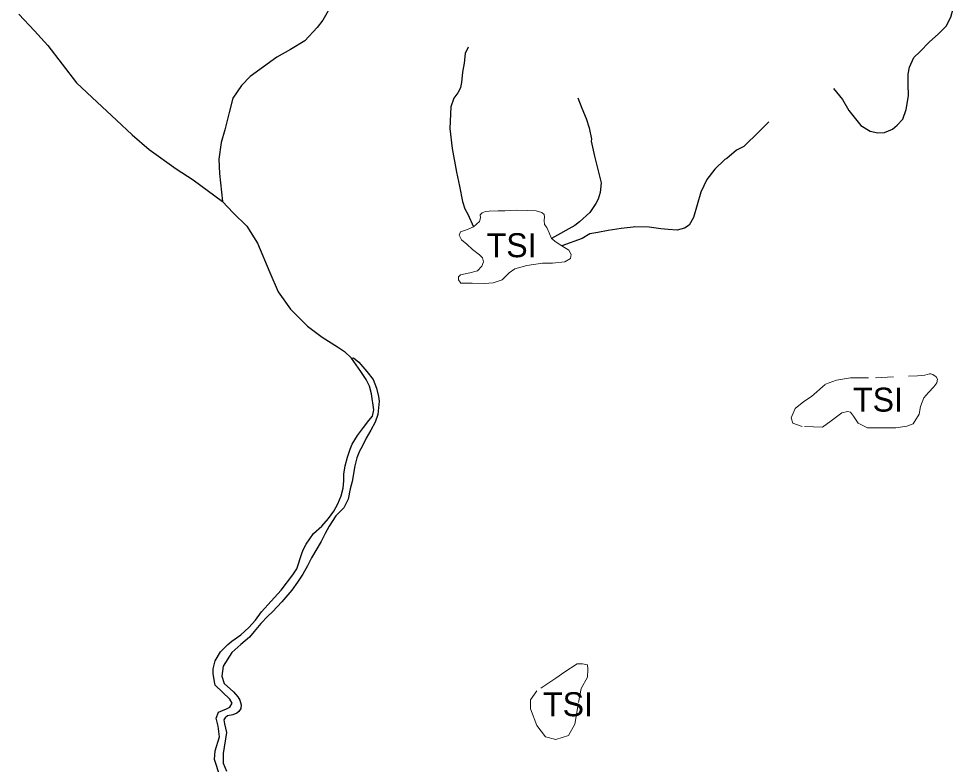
# Model space of a CAD drawing. Extents: x 436.3 to 500.4, y 8231 to 8286.4.
# Drawn here: x 491.46 to 497.73, y 8272.92 to 8277.89 of the extents above; entities that cross this region are included whole.
import ezdxf
from ezdxf.enums import TextEntityAlignment as Align

# ---------------------------------------------------------------- set-up
doc = ezdxf.new("R2010")
doc.units = 0
doc.header["$LTSCALE"] = 0.08
doc.linetypes.add('LONG_DASHED', pattern=[7.5, 6, -1.5])
doc.linetypes.add('SHORT_DASHED', pattern=[2.7, 1.5, -1.2])
for name, color, linetype, lineweight in [('2', 7, 'Continuous', 25), ('21', 7, 'SHORT_DASHED', 13), ('9', 7, 'LONG_DASHED', 25)]:
    doc.layers.add(name, color=color, linetype=linetype, lineweight=lineweight)
doc.layers.add('61', color=7, linetype='Continuous')

msp = doc.modelspace()

# ---------------------------------------------------------------- linework, layer by layer
at = {"layer": '2'}
for points in [[(493.6793, 8275.6241), (493.6916, 8275.6257), (493.7272, 8275.5962), (493.7819, 8275.535), (493.8229, 8275.4802), (493.8449, 8275.4222), (493.8584, 8275.3681), (493.8628, 8275.3366), (493.8538, 8275.2465), (493.8357, 8275.197), (493.8087, 8275.143), (493.7772, 8275.089), (493.7501, 8275.035), (493.7321, 8275.0034), (493.7141, 8274.9584), (493.7005, 8274.9043), (493.6825, 8274.8006), (493.669, 8274.751), (493.6555, 8274.6834), (493.6285, 8274.6248), (493.5744, 8274.5707), (493.5294, 8274.5032), (493.5024, 8274.4536), (493.4754, 8274.3994), (493.4124, 8274.2912), (493.3854, 8274.2371), (493.3538, 8274.1829), (493.3178, 8274.1288), (493.2796, 8274.0754), (493.2143, 8273.998), (493.1513, 8273.9304), (493.1198, 8273.9033), (493.0748, 8273.8537), (493.0298, 8273.7996), (492.9983, 8273.7635), (492.9398, 8273.7139), (492.8813, 8273.6597), (492.8228, 8273.5694), (492.8138, 8273.5016), (492.8294, 8273.4538), (492.8904, 8273.3975), (492.921, 8273.3652), (492.9344, 8273.3415), (492.9423, 8273.3117), (492.9396, 8273.2877), (492.9263, 8273.2663), (492.913, 8273.2557), (492.8864, 8273.2451), (492.8518, 8273.2371), (492.8358, 8273.2238), (492.8278, 8273.2104), (492.8319, 8273.1851), (492.8454, 8273.1263), (492.8229, 8272.9862), (492.8229, 8272.9229), (492.8454, 8272.8686)], [(493.6285, 8274.8504), (493.6375, 8274.9045), (493.651, 8274.9631), (493.669, 8275.0172), (493.6826, 8275.0487), (493.7186, 8275.1072), (493.7592, 8275.1612), (493.7949, 8275.207), (493.8181, 8275.2363), (493.8268, 8275.2781), (493.8133, 8275.3863), (493.7999, 8275.4359), (493.7774, 8275.481), (493.7414, 8275.5352), (493.6793, 8275.6241)], [(493.5249, 8274.5528), (493.5609, 8274.6024), (493.5879, 8274.652), (493.6105, 8274.7061), (493.624, 8274.7557), (493.6285, 8274.8053), (493.6285, 8274.8504)], [(492.8004, 8272.837), (492.7644, 8272.9456), (492.7689, 8273.0043), (492.7982, 8273.0979), (492.789, 8273.1692), (492.7751, 8273.222), (492.7921, 8273.2622), (492.8454, 8273.2846), (492.868, 8273.2967), (492.8835, 8273.323), (492.868, 8273.3494), (492.7688, 8273.4429), (492.7643, 8273.4655), (492.7553, 8273.5198), (492.7553, 8273.5514), (492.7688, 8273.6057), (492.8048, 8273.6644), (492.8543, 8273.714), (492.8813, 8273.7366), (492.9398, 8273.7771), (492.9938, 8273.8268), (493.0388, 8273.8764), (493.0793, 8273.9305), (493.1423, 8274.0027), (493.2098, 8274.0749), (493.2863, 8274.1786), (493.3133, 8274.2192), (493.3493, 8274.3275), (493.3583, 8274.3501), (493.3763, 8274.3816), (493.4258, 8274.4538), (493.4799, 8274.5033), (493.5249, 8274.5528)]]:
    msp.add_lwpolyline(points, dxfattribs=at)
at = {"layer": '21'}
for points in [[(494.5383, 8276.5782), (494.5386, 8276.5592), (494.5331, 8276.5346), (494.4918, 8276.4992)], [(495.0138, 8276.4213), (494.9974, 8276.4597), (494.981, 8276.4954), (494.9673, 8276.5145), (494.9646, 8276.542), (494.9674, 8276.5666), (494.9646, 8276.5803), (494.9482, 8276.594), (494.9098, 8276.605), (494.8548, 8276.6078), (494.7779, 8276.6108), (494.7009, 8276.6055), (494.6569, 8276.6056), (494.5964, 8276.603), (494.5723, 8276.6005), (494.5607, 8276.5972), (494.5516, 8276.593), (494.5383, 8276.5782)], [(494.4918, 8276.4992), (494.445, 8276.48), (494.4065, 8276.4665), (494.3982, 8276.4446), (494.4119, 8276.4117), (494.4476, 8276.3842), (494.486, 8276.3485), (494.5327, 8276.3127), (494.5519, 8276.2935), (494.5601, 8276.2661), (494.5491, 8276.236), (494.5188, 8276.2059), (494.4693, 8276.1923), (494.406, 8276.1787), (494.3923, 8276.1651), (494.3923, 8276.1459), (494.4087, 8276.1239), (494.4829, 8276.1237), (494.5654, 8276.1208), (494.6231, 8276.1262), (494.6836, 8276.1452), (494.7305, 8276.1917), (494.7689, 8276.219), (494.8486, 8276.2408), (494.9531, 8276.257), (495.0191, 8276.2569), (495.1015, 8276.2651), (495.14, 8276.2869), (495.1455, 8276.3143), (495.1291, 8276.3445), (495.0824, 8276.3719)], [(495.0824, 8276.3719), (495.044, 8276.3966), (495.0138, 8276.4213)]]:
    msp.add_lwpolyline(points, dxfattribs=at)
for points in [[(497.544, 8275.5184), (497.5578, 8275.5145), (497.5801, 8275.499), (497.5883, 8275.4842), (497.5851, 8275.4578), (497.5643, 8275.4316), (497.5279, 8275.395), (497.4967, 8275.3583), (497.476, 8275.301), (497.4655, 8275.2488), (497.4265, 8275.1842), (497.3831, 8275.1701), (497.3097, 8275.1597), (497.2421, 8275.1595), (497.1225, 8275.1591), (497.0602, 8275.1903), (497.0291, 8275.2371), (497.0083, 8275.2631), (496.9875, 8275.2682), (496.9511, 8275.2577), (496.8784, 8275.2055), (496.8211, 8275.1636), (496.6859, 8275.1685), (496.6236, 8275.1893), (496.6132, 8275.2258), (496.6392, 8275.2884), (496.6964, 8275.3353), (496.7485, 8275.3668), (496.8421, 8275.4503), (496.9149, 8275.4765), (497.0085, 8275.4924), (497.1747, 8275.4928), (497.4541, 8275.505), (497.5031, 8275.5095), (497.5345, 8275.5183)], [(495.1837, 8273.5843), (495.1028, 8273.5318), (495.0416, 8273.4881), (494.9147, 8273.4035), (494.8724, 8273.3441), (494.8724, 8273.2846), (494.9147, 8273.1742), (494.974, 8273.0978), (495.0417, 8273.0807), (495.1263, 8273.106), (495.1686, 8273.1824), (495.1939, 8273.3267), (495.2108, 8273.4201), (495.2532, 8273.4964), (495.2551, 8273.5484), (495.2527, 8273.5771), (495.2194, 8273.5842)]]:
    msp.add_lwpolyline(points, close=True, dxfattribs=at)
at = {"layer": '9'}
for points in [[(496.8941, 8277.4207), (496.954, 8277.3484), (496.998, 8277.2761), (497.0766, 8277.1754), (497.1397, 8277.1379), (497.1901, 8277.1254), (497.2343, 8277.1287), (497.2879, 8277.151), (497.3195, 8277.1763), (497.3575, 8277.2174), (497.3796, 8277.2806), (497.3956, 8277.3721), (497.3926, 8277.4508), (497.3927, 8277.517), (497.4022, 8277.5643), (497.4307, 8277.6275), (497.4717, 8277.6654), (497.5356, 8277.733), (497.5924, 8277.7836), (497.6461, 8277.8375), (497.6778, 8277.8974), (497.6999, 8277.9794), (497.7095, 8278.0678), (497.7268, 8278.1591)], [(493.5601, 8278.0057), (493.4878, 8277.877), (493.4493, 8277.8295), (493.3675, 8277.739), (493.2713, 8277.6821), (493.18, 8277.6299), (493.0021, 8277.5015), (492.9439, 8277.4421), (492.886, 8277.3563), (492.8619, 8277.2609), (492.8328, 8277.1464), (492.8085, 8277.0606), (492.7939, 8276.9508), (492.7984, 8276.8554), (492.8172, 8276.669)], [(491.4589, 8277.9186), (491.5642, 8277.8054), (491.6534, 8277.7083), (491.8435, 8277.4605), (491.9812, 8277.331), (492.1109, 8277.2096), (492.2164, 8277.1123), (492.3299, 8277.0151), (492.5085, 8276.8851), (492.6222, 8276.8121), (492.8172, 8276.669)], [(494.4572, 8277.6975), (494.4371, 8277.6559), (494.4305, 8277.5908), (494.4204, 8277.53), (494.4136, 8277.4617), (494.407, 8277.4291), (494.4004, 8277.4129), (494.3874, 8277.3934), (494.3611, 8277.3577), (494.3413, 8277.2992), (494.3345, 8277.156), (494.3505, 8277.0225), (494.3797, 8276.8643), (494.3992, 8276.7698), (494.4186, 8276.6688), (494.4349, 8276.6199), (494.4544, 8276.584), (494.4918, 8276.4992)], [(495.1889, 8277.359), (495.215, 8277.2906), (495.2442, 8277.2222), (495.2637, 8277.1604), (495.2806, 8277.0836), (495.2772, 8277.0705), (495.2999, 8276.9696), (495.3453, 8276.7937), (495.3387, 8276.7285), (495.3255, 8276.683), (495.3091, 8276.6537), (495.2698, 8276.595), (495.2011, 8276.5333), (495.1684, 8276.5073), (495.0138, 8276.4213)], [(496.4637, 8277.1991), (496.3983, 8277.1339), (496.2969, 8277.036), (496.2479, 8277.01), (496.1826, 8276.9545), (496.1695, 8276.948), (496.104, 8276.8829), (496.0485, 8276.8144), (496.0091, 8276.7297), (495.9599, 8276.5603), (495.9327, 8276.5098), (495.9, 8276.4903), (495.851, 8276.4772), (495.7923, 8276.4805), (495.7433, 8276.4869), (495.6649, 8276.4967), (495.5669, 8276.5), (495.5571, 8276.4967), (495.4787, 8276.487), (495.3905, 8276.4741), (495.3218, 8276.4611), (495.2695, 8276.4514), (495.2172, 8276.4221), (495.0824, 8276.3719)], [(492.8172, 8276.669), (492.8902, 8276.5926), (492.9795, 8276.5032), (493.0525, 8276.3896), (493.1336, 8276.1946), (493.1903, 8276.0646), (493.2716, 8275.9507), (493.3853, 8275.8366), (493.483, 8275.7632), (493.5844, 8275.6992), (493.6329, 8275.6667), (493.6793, 8275.6241)]]:
    msp.add_lwpolyline(points, dxfattribs=at)

# ---------------------------------------------------------------- texts
at = {"layer": '61'}
for p in [(494.7472, 8276.2965), (497.1917, 8275.2666), (495.1233, 8273.2351)]:
    msp.add_text('TSI', height=0.16, dxfattribs=at).set_placement(p, align=Align.CENTER)

doc.saveas('drawing.dxf')
